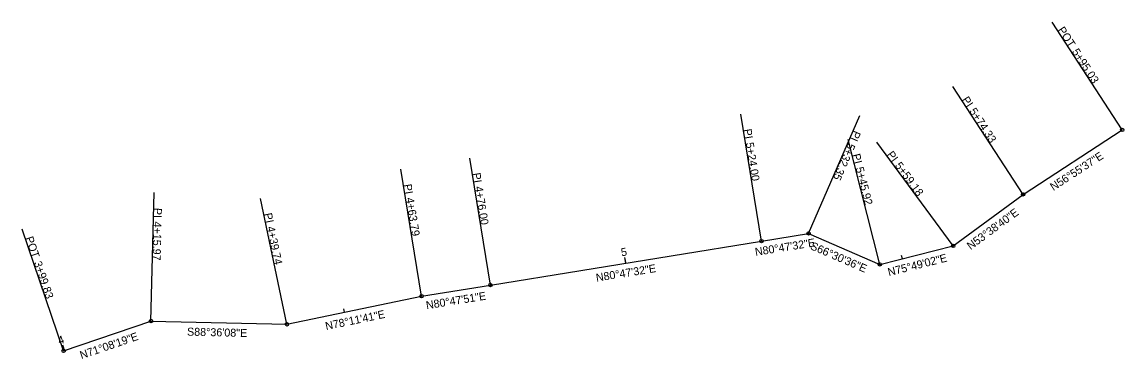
# Model space of a CAD drawing. Extents: x 1963735 to 2341213, y 624302 to 1796154.
# Drawn here: x 2341020.7 to 2341213.4, y 624301.6 to 624360.5 of the extents above; entities that cross this region are included whole.
import ezdxf

# ---------------------------------------------------------------- set-up
doc = ezdxf.new("R2010")
doc.units = 0
for name, color, linetype in [('DR_X_Culvert', 7, 'Continuous'), ('DT_X_Break_Line', 7, 'Continuous'), ('DT_X_Contour_Text', 7, 'Continuous'), ('DT_X_Island', 7, 'Continuous'), ('DT_X_Spot_Elev', 7, 'Continuous'), ('DT_X_TIN_Hull', 7, 'Continuous'), ('DT_X_Triangles', 7, 'Continuous'), ('DT_X_Void', 7, 'Continuous'), ('SV_X_Terrain_Boundary', 7, 'Continuous'), ('SV_X_Terrain_Break_Line', 7, 'Continuous')]:
    doc.layers.add(name, color=color, linetype=linetype)

msp = doc.modelspace()

# ---------------------------------------------------------------- linework, layer by layer
at = {"layer": 'DR_X_Culvert'}
for p, q in [((2341213.1, 624341.63), (2341200.83, 624360.49)), ((2341195.76, 624330.34), (2341183.48, 624349.19)), ((2341150.02, 624322.18), (2341146.42, 624344.39)), ((2341158.26, 624323.52), (2341167.23, 624344.15)), ((2341170.7, 624318.11), (2341165.19, 624339.92)), ((2341183.56, 624321.36), (2341170.22, 624339.48)), ((2341102.63, 624314.5), (2341099.03, 624336.71)), ((2341090.59, 624312.55), (2341086.99, 624334.76)), ((2341043.28, 624308.21), (2341043.83, 624330.7)), ((2341067.05, 624307.63), (2341062.45, 624329.65)), ((2341028.01, 624302.99), (2341020.73, 624324.28))]:
    msp.add_line(p, q, dxfattribs=at)
for centre in [(2341213.1, 624341.63), (2341195.76, 624330.34), (2341150.02, 624322.18), (2341158.26, 624323.52), (2341183.56, 624321.36), (2341170.7, 624318.11), (2341102.63, 624314.5), (2341090.59, 624312.55), (2341043.28, 624308.21), (2341067.05, 624307.63), (2341028.01, 624302.99)]:
    msp.add_circle(centre, 0.3, dxfattribs=at)
at = {"layer": 'DT_X_Break_Line'}
for p, q in [((2341195.76, 624330.34), (2341213.1, 624341.63)), ((2341183.56, 624321.36), (2341195.76, 624330.34)), ((2341102.63, 624314.5), (2341150.02, 624322.18)), ((2341150.02, 624322.18), (2341158.26, 624323.52)), ((2341158.26, 624323.52), (2341170.7, 624318.11)), ((2341170.7, 624318.11), (2341183.56, 624321.36)), ((2341090.59, 624312.55), (2341102.64, 624314.5)), ((2341067.05, 624307.63), (2341090.59, 624312.55)), ((2341028.01, 624302.99), (2341043.28, 624308.21)), ((2341043.28, 624308.21), (2341067.05, 624307.63))]:
    msp.add_line(p, q, dxfattribs=at)
at = {"layer": 'DT_X_Contour_Text'}
for p, q in [((2341126.32, 624318.34), (2341126.16, 624319.33)), ((2341028.17, 624303.05), (2341027.98, 624303.62))]:
    msp.add_line(p, q, dxfattribs=at)
at = {"layer": 'DT_X_Spot_Elev'}
msp.add_line((2341126.32, 624318.34), (2341126.23, 624318.93), dxfattribs=at)
at = {"layer": 'DT_X_Triangles'}
for p, q in [((2341126.32, 624318.34), (2341126.16, 624319.33)), ((2341174.66, 624319.11), (2341174.51, 624319.69)), ((2341077.09, 624309.73), (2341076.97, 624310.32)), ((2341028.17, 624303.05), (2341027.85, 624303.99))]:
    msp.add_line(p, q, dxfattribs=at)
at = {"layer": 'DT_X_Void'}
for p, q in [((2341213.1, 624341.63), (2341200.83, 624360.49)), ((2341195.76, 624330.34), (2341183.48, 624349.19)), ((2341150.02, 624322.18), (2341146.42, 624344.39)), ((2341158.26, 624323.52), (2341167.23, 624344.15)), ((2341170.7, 624318.11), (2341165.19, 624339.92)), ((2341183.56, 624321.36), (2341170.22, 624339.48)), ((2341102.63, 624314.5), (2341099.03, 624336.71)), ((2341090.59, 624312.55), (2341086.99, 624334.76)), ((2341043.28, 624308.21), (2341043.83, 624330.7)), ((2341067.05, 624307.63), (2341062.45, 624329.65)), ((2341028.01, 624302.99), (2341020.73, 624324.28))]:
    msp.add_line(p, q, dxfattribs=at)
for centre in [(2341213.1, 624341.63), (2341195.76, 624330.34), (2341150.02, 624322.18), (2341158.26, 624323.52), (2341183.56, 624321.36), (2341170.7, 624318.11), (2341102.63, 624314.5), (2341090.59, 624312.55), (2341043.28, 624308.21), (2341067.05, 624307.63), (2341028.01, 624302.99)]:
    msp.add_circle(centre, 0.3, dxfattribs=at)
at = {"layer": 'SV_X_Terrain_Boundary'}
for p, q in [((2341213.1, 624341.63), (2341200.83, 624360.49)), ((2341195.76, 624330.34), (2341183.48, 624349.19)), ((2341150.02, 624322.18), (2341146.42, 624344.39)), ((2341158.26, 624323.52), (2341167.23, 624344.15)), ((2341170.7, 624318.11), (2341165.19, 624339.92)), ((2341183.56, 624321.36), (2341170.22, 624339.48)), ((2341102.63, 624314.5), (2341099.03, 624336.71)), ((2341090.59, 624312.55), (2341086.99, 624334.76)), ((2341043.28, 624308.21), (2341043.83, 624330.7)), ((2341067.05, 624307.63), (2341062.45, 624329.65)), ((2341028.01, 624302.99), (2341020.73, 624324.28))]:
    msp.add_line(p, q, dxfattribs=at)
for centre in [(2341213.1, 624341.63), (2341195.76, 624330.34), (2341150.02, 624322.18), (2341158.26, 624323.52), (2341183.56, 624321.36), (2341170.7, 624318.11), (2341102.63, 624314.5), (2341090.59, 624312.55), (2341043.28, 624308.21), (2341067.05, 624307.63), (2341028.01, 624302.99)]:
    msp.add_circle(centre, 0.3, dxfattribs=at)

# ---------------------------------------------------------------- texts
at = {"layer": 'DR_X_Culvert'}
for s, rotation, p in [('POT', 303.073, (2341201.75, 624359.11)), ('5+95.03', 303.073, (2341204.24, 624355.29)), ('PI', 303.073, (2341185, 624346.91)), ('5+74.33', 303.073, (2341186.3, 624344.91)), ('PI', 279.2077, (2341146.88, 624341.7)), ('PI', 246.5099, (2341166.16, 624341.64)), ('5+24.00', 279.2077, (2341147.26, 624339.34)), ('5+32.35', 246.5099, (2341165.21, 624339.45)), ('PI', 284.1829, (2341165.88, 624337.28)), ('PI', 306.3555, (2341171.86, 624337.29)), ('5+59.18', 306.3555, (2341173.28, 624335.37)), ('PI', 279.2077, (2341099.49, 624334.02)), ('5+45.92', 284.1829, (2341166.47, 624334.96)), ('PI', 279.2024, (2341087.45, 624332.05)), ('4+76.00', 279.2077, (2341099.88, 624331.66)), ('4+63.79', 279.2024, (2341087.84, 624329.69)), ('PI', 268.6022, (2341043.79, 624328)), ('PI', 281.8052, (2341063.03, 624326.96)), ('4+15.97', 268.6022, (2341043.73, 624325.61)), ('4+39.74', 281.8052, (2341063.52, 624324.62)), ('POT', 288.8615, (2341021.29, 624322.73)), ('3+99.83', 288.8615, (2341022.77, 624318.41))]:
    msp.add_text(s, height=1.4, rotation=rotation, dxfattribs=at).set_placement(p)
at = {"layer": 'DT_X_Contour_Text'}
msp.add_text('5', height=1.4, rotation=9.2077, dxfattribs=at).set_placement((2341125.57, 624319.51))
at = {"layer": 'DT_X_Island'}
for s, rotation, p in [('N56°55\'37"E', 33.073, (2341201.06, 624330.93)), ('N53°38\'40"E', 36.3555, (2341186.58, 624320.6)), ('N80°47\'32"E', 9.2077, (2341149, 624319.59)), ('S66°30\'36"E', 336.5099, (2341158.44, 624320.82)), ('N80°47\'32"E', 9.2077, (2341121.19, 624315.08)), ('N75°49\'02"E', 14.1829, (2341172.3, 624316.04)), ('N80°47\'51"E', 9.2024, (2341091.48, 624310.26)), ('N78°11\'41"E', 11.8052, (2341073.91, 624306.61)), ('S88°36\'08"E', 358.6022, (2341049.57, 624305.66)), ('N71°08\'19"E', 18.8615, (2341031.13, 624301.52))]:
    msp.add_text(s, height=1.4, rotation=rotation, dxfattribs=at).set_placement(p)
at = {"layer": 'DT_X_TIN_Hull'}
for s, rotation, p in [('N56°55\'37"E', 33.073, (2341201.06, 624330.93)), ('N53°38\'40"E', 36.3555, (2341186.58, 624320.6)), ('N80°47\'32"E', 9.2077, (2341149, 624319.59)), ('S66°30\'36"E', 336.5099, (2341158.44, 624320.82)), ('N80°47\'32"E', 9.2077, (2341121.19, 624315.08)), ('N75°49\'02"E', 14.1829, (2341172.3, 624316.04)), ('N80°47\'51"E', 9.2024, (2341091.48, 624310.26)), ('N78°11\'41"E', 11.8052, (2341073.91, 624306.61)), ('S88°36\'08"E', 358.6022, (2341049.57, 624305.66)), ('N71°08\'19"E', 18.8615, (2341031.13, 624301.52))]:
    msp.add_text(s, height=1.4, rotation=rotation, dxfattribs=at).set_placement(p)
at = {"layer": 'DT_X_Triangles'}
for s, rotation, p in [('5', 9.2077, (2341125.57, 624319.51)), ('4', 18.8615, (2341027.26, 624304.06))]:
    msp.add_text(s, height=1.4, rotation=rotation, dxfattribs=at).set_placement(p)
at = {"layer": 'DT_X_Void'}
for s, rotation, p in [('POT', 303.073, (2341201.75, 624359.11)), ('5+95.03', 303.073, (2341204.24, 624355.29)), ('PI', 303.073, (2341185, 624346.91)), ('5+74.33', 303.073, (2341186.3, 624344.91)), ('PI', 279.2077, (2341146.88, 624341.7)), ('PI', 246.5099, (2341166.16, 624341.64)), ('5+24.00', 279.2077, (2341147.26, 624339.34)), ('5+32.35', 246.5099, (2341165.21, 624339.45)), ('PI', 284.1829, (2341165.88, 624337.28)), ('PI', 306.3555, (2341171.86, 624337.29)), ('5+59.18', 306.3555, (2341173.28, 624335.37)), ('PI', 279.2077, (2341099.49, 624334.02)), ('5+45.92', 284.1829, (2341166.47, 624334.96)), ('PI', 279.2024, (2341087.45, 624332.05)), ('4+76.00', 279.2077, (2341099.88, 624331.66)), ('4+63.79', 279.2024, (2341087.84, 624329.69)), ('PI', 268.6022, (2341043.79, 624328)), ('PI', 281.8052, (2341063.03, 624326.96)), ('4+15.97', 268.6022, (2341043.73, 624325.61)), ('4+39.74', 281.8052, (2341063.52, 624324.62)), ('POT', 288.8615, (2341021.29, 624322.73)), ('3+99.83', 288.8615, (2341022.77, 624318.41))]:
    msp.add_text(s, height=1.4, rotation=rotation, dxfattribs=at).set_placement(p)
at = {"layer": 'SV_X_Terrain_Boundary'}
for s, rotation, p in [('POT', 303.073, (2341201.75, 624359.11)), ('5+95.03', 303.073, (2341204.24, 624355.29)), ('PI', 303.073, (2341185, 624346.91)), ('5+74.33', 303.073, (2341186.3, 624344.91)), ('PI', 279.2077, (2341146.88, 624341.7)), ('PI', 246.5099, (2341166.16, 624341.64)), ('5+24.00', 279.2077, (2341147.26, 624339.34)), ('5+32.35', 246.5099, (2341165.21, 624339.45)), ('PI', 284.1829, (2341165.88, 624337.28)), ('PI', 306.3555, (2341171.86, 624337.29)), ('5+59.18', 306.3555, (2341173.28, 624335.37)), ('PI', 279.2077, (2341099.49, 624334.02)), ('5+45.92', 284.1829, (2341166.47, 624334.96)), ('PI', 279.2024, (2341087.45, 624332.05)), ('4+76.00', 279.2077, (2341099.88, 624331.66)), ('4+63.79', 279.2024, (2341087.84, 624329.69)), ('PI', 268.6022, (2341043.79, 624328)), ('PI', 281.8052, (2341063.03, 624326.96)), ('4+15.97', 268.6022, (2341043.73, 624325.61)), ('4+39.74', 281.8052, (2341063.52, 624324.62)), ('POT', 288.8615, (2341021.29, 624322.73)), ('3+99.83', 288.8615, (2341022.77, 624318.41))]:
    msp.add_text(s, height=1.4, rotation=rotation, dxfattribs=at).set_placement(p)
at = {"layer": 'SV_X_Terrain_Break_Line'}
for s, rotation, p in [('N56°55\'37"E', 33.073, (2341201.06, 624330.93)), ('N53°38\'40"E', 36.3555, (2341186.58, 624320.6)), ('N80°47\'32"E', 9.2077, (2341149, 624319.59)), ('S66°30\'36"E', 336.5099, (2341158.44, 624320.82)), ('N80°47\'32"E', 9.2077, (2341121.19, 624315.08)), ('N75°49\'02"E', 14.1829, (2341172.3, 624316.04)), ('N80°47\'51"E', 9.2024, (2341091.48, 624310.26)), ('N78°11\'41"E', 11.8052, (2341073.91, 624306.61)), ('S88°36\'08"E', 358.6022, (2341049.57, 624305.66)), ('N71°08\'19"E', 18.8615, (2341031.13, 624301.52))]:
    msp.add_text(s, height=1.4, rotation=rotation, dxfattribs=at).set_placement(p)

doc.saveas('drawing.dxf')
